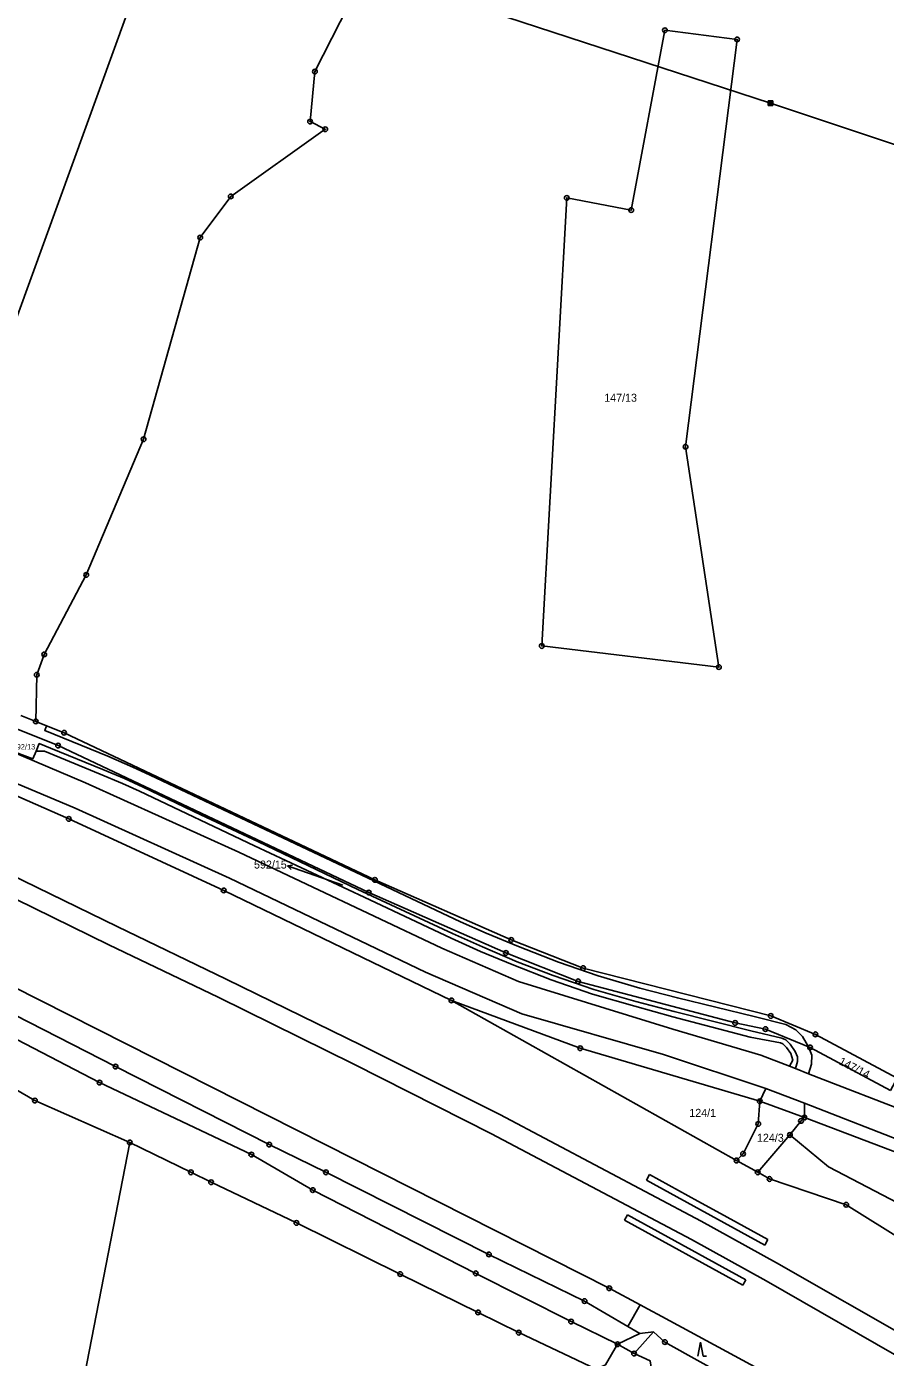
# Model space of a CAD drawing. Extents: x -758582 to -751794, y -998770 to -994350.
# Drawn here: x -754793.1 to -754610.6, y -996434.2 to -996151.5 of the extents above; entities that cross this region are included whole.
import ezdxf

# ---------------------------------------------------------------- set-up
doc = ezdxf.new("R2010")
doc.units = 0
for name, color, linetype in [('Hranice parcel', 7, 'Continuous'), ('Parcelní čísla', 7, 'Continuous'), ('Pop  PČ popisy', 7, 'Continuous'), ('Poz předměty', 7, 'Continuous'), ('Vnitřní kresba', 7, 'Continuous'), ('Značky bodu BP', 7, 'Continuous'), ('Značky kultur', 7, 'Continuous')]:
    doc.layers.add(name, color=color, linetype=linetype)

msp = doc.modelspace()

# ---------------------------------------------------------------- linework, layer by layer
at = {"layer": 'Hranice parcel'}
for p, q in [((-754791.17, -996299.09), (-754794.37, -996297.81)), ((-754791.17, -996299.09), (-754788.86, -996300.01)), ((-754702.84, -996358.33), (-754642.22, -996392.35)), ((-754637.3, -996379.76), (-754627.79, -996383.24)), ((-754630.89, -996386.93), (-754637.74, -996394.86)), ((-754807.71, -996575.72), (-754771.19, -996388.52)), ((-754637.74, -996394.86), (-754642.22, -996392.35)), ((-754665.34, -996427.62), (-754662.74, -996423.01))]:
    msp.add_line(p, q, dxfattribs=at)
for points in [[(-754821.23, -996284.89), (-754765.97, -996132.74), (-754709.63, -995977.66), (-754653.3, -995822.57), (-754611.67, -995707.97)], [(-754459.14, -995820.99), (-754420.8, -995995.5), (-754512.18, -995990.16), (-754547.22, -995985.93), (-754586.5, -995976.79), (-754639.91, -995962.86), (-754658.71, -996007.21), (-754671.95, -996004.02), (-754681.09, -996005.78), (-754686.14, -996012.49), (-754701.82, -996096.06), (-754703.29, -996100.58), (-754713.95, -996125.81), (-754731.84, -996161.03), (-754732.87, -996171.66), (-754729.63, -996173.28), (-754749.73, -996187.55), (-754756.22, -996196.29), (-754768.24, -996239.12), (-754780.45, -996267.96), (-754789.36, -996284.83), (-754790.97, -996289.17), (-754791.17, -996299.09)], [(-754662.74, -996423.01), (-754669.27, -996419.49), (-754844.58, -996330.92), (-754994, -996258.05), (-755001.55, -996254.28), (-755006.45, -996251.84), (-755142.05, -996184.14), (-755275.65, -996117.2), (-755276.76, -996116.66)], [(-754665.34, -996427.62), (-754674.53, -996422.22), (-754694.85, -996412.29), (-754729.49, -996394.86), (-754741.54, -996388.96), (-754774.22, -996372.4), (-754807.91, -996355.15), (-754858.97, -996329.54), (-754909.75, -996305.36), (-755002.67, -996257.49), (-755008.53, -996254.77), (-755134.52, -996193.78), (-755139.66, -996190.08), (-755206.85, -996155.12), (-755212.53, -996152.36), (-755248.45, -996133.62), (-755275.54, -996119.52), (-755277.31, -996118.28)], [(-754683.62, -996283.05), (-754678.3, -996187.87), (-754664.61, -996190.46), (-754657.45, -996152.24), (-754642.12, -996154.19), (-754653.07, -996240.72), (-754645.98, -996287.53), (-754683.62, -996283.05)], [(-754923.36, -996177.42), (-754890.48, -996216.15), (-754868.81, -996242.57), (-754848.08, -996264.54), (-754841.54, -996269.8), (-754830.6, -996281.24), (-754822.3, -996287.83), (-754811.04, -996294.35), (-754786.41, -996304.22), (-754720.4, -996335.43), (-754691.23, -996348.26), (-754675.91, -996354.29), (-754642.53, -996363.12), (-754636.09, -996364.43), (-754626.93, -996368.19)], [(-754667.51, -996431.39), (-754677.38, -996426.56), (-754697.67, -996416.32), (-754732.31, -996398.65), (-754745.35, -996391.09), (-754777.62, -996375.81), (-754811.07, -996358.46), (-754861.11, -996332.99), (-754911.17, -996307.35), (-755005.33, -996262.98), (-755011.09, -996260.31), (-755135.67, -996198.2), (-755141.62, -996197.74)], [(-754702.84, -996358.33), (-754751.23, -996334.98), (-754784.15, -996319.77), (-754807.86, -996309.34), (-754832.04, -996297.57)], [(-754626.93, -996368.19), (-754628.23, -996366.03), (-754629.63, -996364.59), (-754631.77, -996363.47), (-754638.48, -996361.77), (-754654.81, -996357.81), (-754662.78, -996355.72), (-754671.67, -996353.13), (-754680.05, -996350.24), (-754688.6, -996346.88), (-754695.45, -996344.06), (-754700.93, -996341.66), (-754719.31, -996332.93), (-754742.43, -996322), (-754766.86, -996310.47), (-754770.52, -996308.76), (-754775.88, -996306.47), (-754789.26, -996301.03), (-754788.86, -996300.01)], [(-754788.86, -996300.01), (-754785.16, -996301.49), (-754719.09, -996332.73), (-754690.11, -996345.48), (-754674.83, -996351.49), (-754634.95, -996361.65), (-754625.47, -996365.55), (-754608.08, -996374.84), (-754609.52, -996377.47)], [(-754791.08, -996305.41), (-754791.76, -996306.99), (-754797.23, -996304.96), (-754796.46, -996303.03)], [(-754791.08, -996305.41), (-754790.41, -996303.79), (-754788.07, -996304.74), (-754776.89, -996309.27), (-754772.34, -996311.21), (-754768.35, -996313.07), (-754756.07, -996318.95), (-754743.81, -996324.64), (-754722.73, -996334.77), (-754702.6, -996344.16), (-754696.23, -996346.99), (-754688.82, -996350.13), (-754681.17, -996353.03), (-754672.53, -996355.99), (-754663.64, -996358.59), (-754655.5, -996360.73), (-754639.2, -996364.79), (-754632.58, -996366.33), (-754631.72, -996366.75), (-754630.82, -996367.63), (-754629.74, -996369.23), (-754629.3, -996370.36), (-754629.26, -996371.31), (-754629.73, -996372.81)], [(-754629.73, -996372.81), (-754630.95, -996372.33), (-754630.27, -996371.02), (-754630.67, -996369.62), (-754631.63, -996368.33), (-754632.37, -996367.56), (-754632.92, -996367.32), (-754639.37, -996366.12), (-754655.74, -996361.84), (-754663.87, -996359.59), (-754672.86, -996356.99), (-754681.61, -996353.99), (-754689.89, -996350.72), (-754696.65, -996347.97), (-754702.91, -996345.12), (-754721.34, -996336.42), (-754744.71, -996325.49), (-754769.11, -996313.9), (-754772.74, -996312.29), (-754777.5, -996310.27), (-754789.33, -996305.42), (-754791.08, -996305.41)], [(-754771.19, -996388.52), (-754791.36, -996379.62), (-754816.32, -996365.21), (-754835.87, -996356.92), (-754867.49, -996343.66), (-754870.86, -996341.95)], [(-754637.3, -996379.76), (-754675.46, -996368.51), (-754702.84, -996358.33)], [(-754626.93, -996368.19), (-754626.24, -996369.98), (-754626.33, -996371.88), (-754626.92, -996373.91), (-754629.73, -996372.81)], [(-754609.52, -996377.47), (-754626.61, -996368.32), (-754626.93, -996368.19)], [(-754642.22, -996392.35), (-754640.85, -996390.91), (-754637.61, -996384.57), (-754637.3, -996379.76)], [(-754627.79, -996383.24), (-754628.53, -996383.94), (-754630.89, -996386.93)], [(-754380.19, -996552.13), (-754385.25, -996519.98), (-754387.72, -996506.25), (-754392.07, -996496.35), (-754394.77, -996491.32), (-754402.71, -996478.9), (-754429.39, -996448.06), (-754441.07, -996434.06), (-754445.75, -996429.16), (-754451.91, -996425.8), (-754462.97, -996420.4), (-754475.9, -996417.42), (-754494.23, -996413.79), (-754532.74, -996409.39), (-754543.79, -996407.71), (-754566.79, -996404.2), (-754576.27, -996402.41), (-754594.78, -996395.73), (-754627.79, -996383.24)], [(-754630.89, -996386.93), (-754622.69, -996393.73), (-754540.76, -996436.36), (-754489.08, -996468.96), (-754461.34, -996488.31), (-754439.14, -996506.23), (-754383.88, -996547.82), (-754380.19, -996552.13)], [(-754771.19, -996388.52), (-754758.21, -996394.86), (-754753.9, -996396.97), (-754735.77, -996405.6), (-754713.69, -996416.49), (-754697.17, -996424.63), (-754688.53, -996428.92), (-754672.06, -996436.7), (-754670.11, -996435.73), (-754667.51, -996431.39)], [(-754376, -996565.84), (-754445.23, -996512.86), (-754489.02, -996482.87), (-754618.93, -996401.76), (-754635.21, -996396.28), (-754637.74, -996394.86)], [(-754662.74, -996423.01), (-754660.99, -996423.95), (-754658.11, -996425.51), (-754627.2, -996442.18), (-754623.88, -996443.97), (-754620.28, -996448.06)], [(-754619.53, -996455.97), (-754621.68, -996454.82), (-754625.51, -996448.75), (-754657.45, -996430.93), (-754659.9, -996428.77), (-754662.79, -996429.12), (-754665.34, -996427.62)], [(-754667.51, -996431.39), (-754664, -996433.37), (-754660.57, -996434.91), (-754659.25, -996443.61), (-754658.02, -996448.93), (-754655.6, -996457.96), (-754651.54, -996475.12), (-754646.09, -996505.52), (-754646.03, -996511.83), (-754644.79, -996515.65)]]:
    msp.add_lwpolyline(points, dxfattribs=at)
at = {"layer": 'Pop  PČ popisy'}
for p, q in [((-754737.69, -996329.74), (-754736.58, -996329.6)), ((-754734.85, -996330.72), (-754737.69, -996329.74)), ((-754737.69, -996329.74), (-754736.9, -996330.54)), ((-754725.92, -996333.83), (-754734.85, -996330.72))]:
    msp.add_line(p, q, dxfattribs=at)
at = {"layer": 'Poz předměty'}
for p, q in [((-754786.06, -996118.44), (-754635.04, -996167.71)), ((-754635.54, -996167.21), (-754634.54, -996167.21)), ((-754635.54, -996168.21), (-754635.54, -996167.21)), ((-754635.54, -996167.41), (-754634.54, -996167.41)), ((-754635.54, -996167.61), (-754634.54, -996167.61)), ((-754635.34, -996168.21), (-754635.34, -996167.21)), ((-754635.14, -996168.21), (-754635.14, -996167.21)), ((-754516.72, -996207.25), (-754635.04, -996167.71)), ((-754634.94, -996168.21), (-754634.94, -996167.21)), ((-754634.74, -996168.21), (-754634.74, -996167.21)), ((-754634.54, -996168.21), (-754634.54, -996167.21)), ((-754635.54, -996167.81), (-754634.54, -996167.81)), ((-754635.54, -996168.01), (-754634.54, -996168.01)), ((-754635.54, -996168.21), (-754634.54, -996168.21)), ((-754773.87, -996342.63), (-754809.59, -996325.3)), ((-754775.66, -996346.56), (-754811.29, -996329.05)), ((-754750.68, -996353.86), (-754773.87, -996342.63)), ((-754752.43, -996357.68), (-754775.66, -996346.56)), ((-754721.84, -996367.95), (-754750.68, -996353.86)), ((-754723.54, -996371.91), (-754752.43, -996357.68)), ((-754692.54, -996382.61), (-754721.84, -996367.95)), ((-754694.3, -996386.65), (-754723.54, -996371.91)), ((-754649.76, -996405.23), (-754692.54, -996382.61)), ((-754651.81, -996409.13), (-754694.3, -996386.65)), ((-754633.76, -996414.06), (-754649.76, -996405.23)), ((-754635.9, -996417.94), (-754651.81, -996409.13)), ((-754602.64, -996431.86), (-754633.76, -996414.06)), ((-754604.81, -996435.76), (-754635.9, -996417.94))]:
    msp.add_line(p, q, dxfattribs=at)
at = {"layer": 'Vnitřní kresba'}
for p, q in [((-754782.81, -996317.5), (-754817.2, -996303.06)), ((-754804.59, -996301.93), (-754780.59, -996312.15)), ((-754747.98, -996326.83), (-754780.59, -996312.15)), ((-754749.96, -996332.35), (-754782.81, -996317.5)), ((-754704.86, -996347.23), (-754747.98, -996326.83)), ((-754708.35, -996352.37), (-754749.96, -996332.35)), ((-754688.59, -996354.35), (-754704.86, -996347.23)), ((-754687.88, -996361.19), (-754708.35, -996352.37)), ((-754655.77, -996364.42), (-754688.59, -996354.35)), ((-754657.72, -996369.81), (-754687.88, -996361.19)), ((-754637.06, -996369.95), (-754655.77, -996364.42)), ((-754635.99, -996377.07), (-754657.72, -996369.81)), ((-754637.06, -996369.95), (-754630.95, -996372.33)), ((-754626.92, -996373.91), (-754601.91, -996383.66)), ((-754637.3, -996379.76), (-754635.99, -996377.07)), ((-754627.82, -996380.15), (-754635.99, -996377.07)), ((-754627.79, -996383.24), (-754627.82, -996380.15)), ((-754604.92, -996389.09), (-754627.82, -996380.15)), ((-754661.36, -996396.51), (-754660.7, -996395.32)), ((-754636.25, -996410.36), (-754661.36, -996396.51)), ((-754650.43, -996400.98), (-754660.7, -996395.32)), ((-754645.62, -996403.64), (-754650.43, -996400.98)), ((-754665.44, -996403.9), (-754666.06, -996405.04)), ((-754666.06, -996405.04), (-754655.84, -996410.64)), ((-754640.26, -996417.69), (-754665.44, -996403.9)), ((-754645.62, -996403.64), (-754635.59, -996409.16)), ((-754650.95, -996413.32), (-754655.84, -996410.64)), ((-754636.25, -996410.36), (-754635.59, -996409.16)), ((-754640.88, -996418.83), (-754650.95, -996413.32)), ((-754640.26, -996417.69), (-754640.88, -996418.83)), ((-754662.79, -996429.12), (-754667.51, -996431.39)), ((-754664, -996433.37), (-754659.9, -996428.77))]:
    msp.add_line(p, q, dxfattribs=at)
at = {"layer": 'Značky bodu BP'}
for centre, radius in [((-754657.45, -996152.24), 0.5), ((-754657.45, -996152.24), 0.0303), ((-754642.12, -996154.19), 0.5), ((-754642.12, -996154.19), 0.0303), ((-754731.84, -996161.03), 0.5), ((-754731.84, -996161.03), 0.0303), ((-754732.87, -996171.66), 0.5), ((-754732.87, -996171.66), 0.0303), ((-754729.63, -996173.28), 0.5), ((-754729.63, -996173.28), 0.0303), ((-754749.73, -996187.55), 0.5), ((-754749.73, -996187.55), 0.0303), ((-754678.3, -996187.87), 0.5), ((-754678.3, -996187.87), 0.0303), ((-754664.61, -996190.46), 0.5), ((-754664.61, -996190.46), 0.0303), ((-754756.22, -996196.29), 0.5), ((-754756.22, -996196.29), 0.0303), ((-754768.24, -996239.12), 0.5), ((-754768.24, -996239.12), 0.0303), ((-754653.07, -996240.72), 0.5), ((-754653.07, -996240.72), 0.0303), ((-754780.45, -996267.96), 0.5), ((-754780.45, -996267.96), 0.0303), ((-754683.62, -996283.05), 0.5), ((-754683.62, -996283.05), 0.0303), ((-754789.36, -996284.83), 0.5), ((-754789.36, -996284.83), 0.0303), ((-754790.97, -996289.17), 0.5), ((-754790.97, -996289.17), 0.0303), ((-754645.98, -996287.53), 0.5), ((-754645.98, -996287.53), 0.0303), ((-754791.17, -996299.09), 0.5), ((-754791.17, -996299.09), 0.0303), ((-754785.16, -996301.49), 0.5), ((-754785.16, -996301.49), 0.0303), ((-754786.41, -996304.22), 0.5), ((-754786.41, -996304.22), 0.0303), ((-754784.15, -996319.77), 0.5), ((-754784.15, -996319.77), 0.0303), ((-754751.23, -996334.98), 0.5), ((-754719.09, -996332.73), 0.5), ((-754719.09, -996332.73), 0.0303), ((-754751.23, -996334.98), 0.0303), ((-754720.4, -996335.43), 0.5), ((-754720.4, -996335.43), 0.0303), ((-754690.11, -996345.48), 0.5), ((-754690.11, -996345.48), 0.0303), ((-754691.23, -996348.26), 0.5), ((-754691.23, -996348.26), 0.0303), ((-754674.83, -996351.49), 0.5), ((-754674.83, -996351.49), 0.0303), ((-754675.91, -996354.29), 0.5), ((-754675.91, -996354.29), 0.0303), ((-754702.84, -996358.33), 0.5), ((-754702.84, -996358.33), 0.0303), ((-754642.53, -996363.12), 0.5), ((-754634.95, -996361.65), 0.5), ((-754634.95, -996361.65), 0.0303), ((-754642.53, -996363.12), 0.0303), ((-754636.09, -996364.43), 0.5), ((-754636.09, -996364.43), 0.0303), ((-754625.47, -996365.55), 0.5), ((-754625.47, -996365.55), 0.0303), ((-754675.46, -996368.51), 0.5), ((-754626.61, -996368.32), 0.5), ((-754626.61, -996368.32), 0.0303), ((-754675.46, -996368.51), 0.0303), ((-754774.22, -996372.4), 0.5), ((-754774.22, -996372.4), 0.0303), ((-754777.62, -996375.81), 0.5), ((-754777.62, -996375.81), 0.0303), ((-754791.36, -996379.62), 0.5), ((-754791.36, -996379.62), 0.0303), ((-754637.3, -996379.76), 0.5), ((-754637.3, -996379.76), 0.0303), ((-754637.61, -996384.57), 0.5), ((-754637.61, -996384.57), 0.0303), ((-754628.53, -996383.94), 0.5), ((-754628.53, -996383.94), 0.0303), ((-754627.79, -996383.24), 0.5), ((-754627.79, -996383.24), 0.0303), ((-754771.19, -996388.52), 0.5), ((-754630.89, -996386.93), 0.5), ((-754630.89, -996386.93), 0.0303), ((-754771.19, -996388.52), 0.0303), ((-754745.35, -996391.09), 0.5), ((-754745.35, -996391.09), 0.0303), ((-754741.54, -996388.96), 0.5), ((-754741.54, -996388.96), 0.0303), ((-754640.85, -996390.91), 0.5), ((-754640.85, -996390.91), 0.0303), ((-754642.22, -996392.35), 0.5), ((-754642.22, -996392.35), 0.0303), ((-754758.21, -996394.86), 0.5), ((-754758.21, -996394.86), 0.0303), ((-754753.9, -996396.97), 0.5), ((-754729.49, -996394.86), 0.5), ((-754729.49, -996394.86), 0.0303), ((-754637.74, -996394.86), 0.5), ((-754637.74, -996394.86), 0.0303), ((-754635.21, -996396.28), 0.5), ((-754635.21, -996396.28), 0.0303), ((-754753.9, -996396.97), 0.0303), ((-754732.31, -996398.65), 0.5), ((-754732.31, -996398.65), 0.0303), ((-754618.93, -996401.76), 0.5), ((-754618.93, -996401.76), 0.0303), ((-754735.77, -996405.6), 0.5), ((-754735.77, -996405.6), 0.0303), ((-754694.85, -996412.29), 0.5), ((-754694.85, -996412.29), 0.0303), ((-754713.69, -996416.49), 0.5), ((-754713.69, -996416.49), 0.0303), ((-754697.67, -996416.32), 0.5), ((-754697.67, -996416.32), 0.0303), ((-754669.27, -996419.49), 0.5), ((-754674.53, -996422.22), 0.5), ((-754669.27, -996419.49), 0.0303), ((-754697.17, -996424.63), 0.5), ((-754697.17, -996424.63), 0.0303), ((-754674.53, -996422.22), 0.0303), ((-754677.38, -996426.56), 0.5), ((-754677.38, -996426.56), 0.0303), ((-754688.53, -996428.92), 0.5), ((-754688.53, -996428.92), 0.0303), ((-754657.45, -996430.93), 0.5), ((-754667.51, -996431.39), 0.5), ((-754667.51, -996431.39), 0.0303), ((-754664, -996433.37), 0.5), ((-754664, -996433.37), 0.0303), ((-754657.45, -996430.93), 0.0303)]:
    msp.add_circle(centre, radius, dxfattribs=at)
at = {"layer": 'Značky kultur'}
for p, q in [((-754649.9, -996430.94), (-754650.46, -996433.94)), ((-754649.34, -996433.94), (-754649.9, -996430.94)), ((-754649.34, -996433.94), (-754648.59, -996433.94))]:
    msp.add_line(p, q, dxfattribs=at)

# ---------------------------------------------------------------- texts
at = {"layer": 'Parcelní čísla'}
for s, height, p in [('147/13', 1.7, (-754670.35, -996231.16)), ('592/13', 1.139, (-754796.09, -996305.03)), ('592/15', 1.7, (-754744.78, -996330.33)), ('124/1', 1.7, (-754652.27, -996383.08)), ('124/3', 1.7, (-754637.89, -996388.37))]:
    msp.add_text(s, height=height, dxfattribs=at).set_placement(p)
msp.add_text('147/14', height=1.7, rotation=333, dxfattribs=at).set_placement((-754620.65, -996371.83))

doc.saveas('drawing.dxf')
